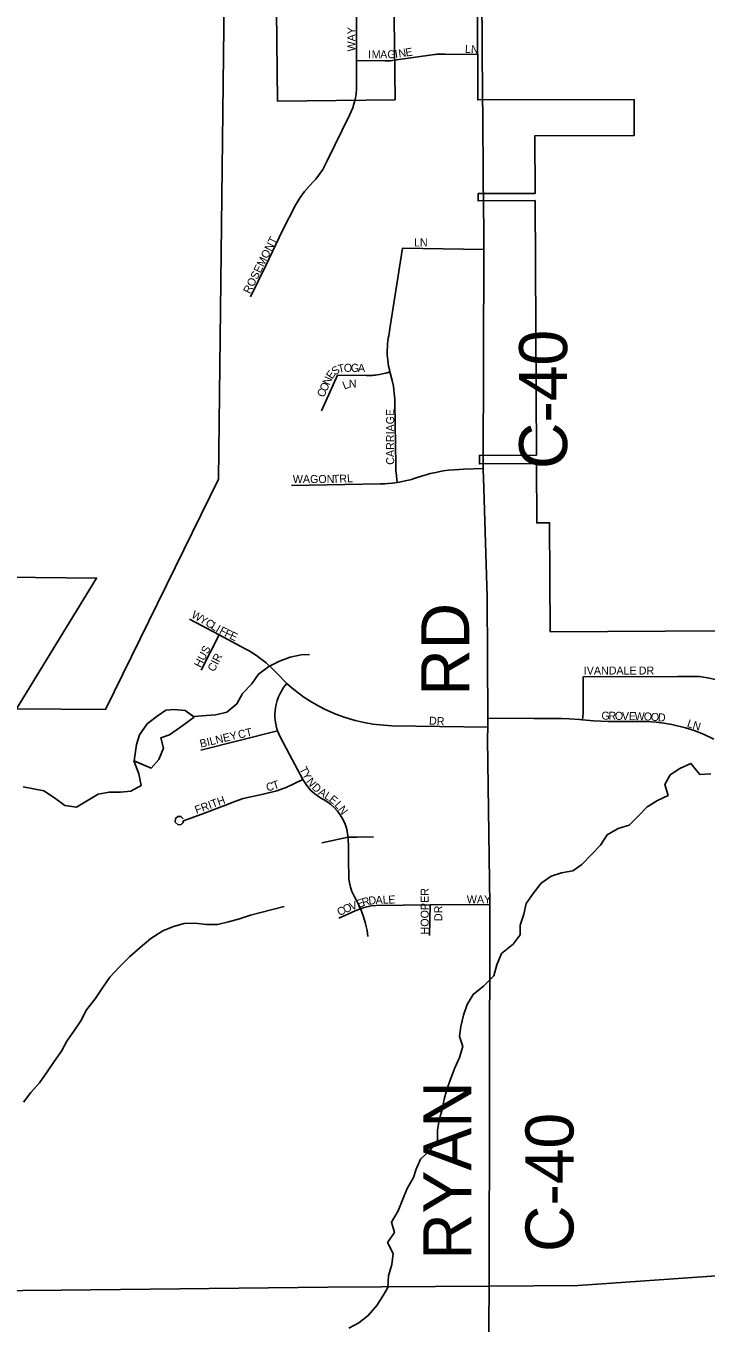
# Model space of a CAD drawing. Extents: x 1985906 to 2277390, y 930619 to 1324581.
# Drawn here: x 2135458 to 2139705, y 1129372 to 1137477 of the extents above; entities that cross this region are included whole.
import ezdxf

# ---------------------------------------------------------------- set-up
doc = ezdxf.new("R2010")
doc.units = 0
for name, color, linetype in [('GM_X_City_Street', 7, 'Continuous'), ('GM_X_Corporation', 7, 'Continuous'), ('GM_X_County_Road', 7, 'Continuous'), ('GM_X_County_Road_Text', 7, 'Continuous'), ('GM_X_Minor_Lake', 7, 'Continuous'), ('GM_X_Minor_River', 7, 'Continuous'), ('GM_X_State_Route', 7, 'Continuous'), ('GM_X_Township_Road', 7, 'Continuous'), ('GM_X_Township_Subdivision', 7, 'Continuous'), ('GM_X_Township_Subdivision_Text', 7, 'Continuous')]:
    doc.layers.add(name, color=color, linetype=linetype)

msp = doc.modelspace()

# ---------------------------------------------------------------- linework, layer by layer
at = {"layer": 'GM_X_City_Street'}
msp.add_lwpolyline([(2138315.1, 1134652.6), (2138313.4, 1134704.1)], dxfattribs=at)
at = {"layer": 'GM_X_Corporation'}
for points in [[(2136709.2, 1138705.4), (2136660.1, 1134644.9), (2135955.2, 1133206.6), (2135398.4, 1133209.2), (2135899.2, 1134027.1), (2135327.8, 1134032.4), (2135329.8, 1133491.3), (2133808.1, 1133465.9), (2133806.7, 1133847.6), (2132416.1, 1133842.6), (2132394.6, 1139746.5)], [(2137743.9, 1138716.9), (2137763, 1137016.1), (2137028.7, 1137007.9), (2137009.7, 1138708.7)], [(2139807.8, 1133697.6), (2138732, 1133691.9), (2138728.5, 1134372.3), (2138648.4, 1134371.9), (2138646.5, 1134742.1), (2138290.3, 1134740.2), (2138290.1, 1134793.3), (2138646.2, 1134795.2), (2138637.9, 1136386), (2138281.9, 1136384.2), (2138281.7, 1136429.2), (2138637.9, 1136430.7), (2138636.4, 1136790.9), (2139256.6, 1136793.4), (2139255.7, 1137018.5), (2138279.5, 1137014.5), (2138277.3, 1137590.2)]]:
    msp.add_lwpolyline(points, dxfattribs=at)
at = {"layer": 'GM_X_County_Road'}
for points in [[(2138306.9, 1137435.1), (2138305.7, 1137589.7)], [(2138311.6, 1136868.3), (2138308, 1137299.1), (2138306.9, 1137435.1)], [(2138316.5, 1136301.5), (2138311.6, 1136868.3)], [(2138313.4, 1134704.1), (2138313.1, 1134711.8), (2138318.4, 1136080.9), (2138316.9, 1136250)], [(2138316.9, 1136250), (2138316.5, 1136301.5)], [(2138351.4, 1129603.3), (2138354.8, 1131986.4), (2138341.2, 1133022.6), (2138341.8, 1133095.5), (2138341.6, 1133150.7), (2138339.2, 1133910.2), (2138315.1, 1134652.6)]]:
    msp.add_lwpolyline(points, dxfattribs=at)
at = {"layer": 'GM_X_Minor_Lake'}
for points in [[(2136131.4, 1132885.3), (2136240.6, 1132839.3), (2136288.7, 1132893.6), (2136316.5, 1132963.8), (2136300.2, 1133028), (2136354.4, 1133048.2), (2136416.5, 1133090.5), (2136508.4, 1133157.6)], [(2136510.7, 1133156.9), (2136452.3, 1133198.9), (2136381.9, 1133206.7), (2136331.7, 1133200.6), (2136277.6, 1133164.3), (2136215.5, 1133116), (2136167.5, 1133047.7), (2136147.7, 1132987.4), (2136133.5, 1132884.2)], [(2136509, 1133158.1), (2136452.3, 1133198.9), (2136381.9, 1133206.7), (2136331.7, 1133200.6), (2136277.6, 1133164.3), (2136215.5, 1133116), (2136167.5, 1133047.7), (2136147.7, 1132987.4), (2136133.6, 1132884.4)], [(2136133.6, 1132884.4), (2136240.6, 1132839.3), (2136288.7, 1132893.6), (2136316.5, 1132963.8), (2136300.2, 1133028), (2136354.4, 1133048.2), (2136416.5, 1133090.5), (2136509, 1133158.1)]]:
    msp.add_lwpolyline(points, dxfattribs=at)
at = {"layer": 'GM_X_Minor_River'}
for points in [[(2136509.5, 1133162), (2136584.3, 1133168.5), (2136644.7, 1133173.4), (2136713.3, 1133188.3), (2136774.5, 1133241.3), (2136809.7, 1133304.9), (2136869, 1133366), (2136910.3, 1133427.5), (2136975.4, 1133474.4), (2137042.2, 1133507.3), (2137109, 1133532.2), (2137177.5, 1133547), (2137227.8, 1133550.1)], [(2135441.5, 1132721.7), (2135505.6, 1132710.5), (2135569.7, 1132697.3), (2135637.2, 1132654), (2135700.7, 1132606.7), (2135772.8, 1132595.3), (2135845.9, 1132640.2), (2135908.9, 1132677.1), (2135977.4, 1132689.9), (2136047.7, 1132688.7), (2136112.1, 1132695.5), (2136177, 1132730.5), (2136162.1, 1132803), (2136132.4, 1132884.2)], [(2137474.1, 1129340.5), (2137536.9, 1129373.4), (2137596, 1129418.5), (2137649.3, 1129481.8), (2137688.6, 1129543.3), (2137717.6, 1129594.9), (2137722.9, 1129667), (2137742.1, 1129736.9), (2137751.4, 1129806.9), (2137716.4, 1129875.8), (2137759.7, 1129937.2), (2137740.7, 1130001.8), (2137782.1, 1130073.2), (2137811.5, 1130144.9), (2137838.8, 1130212.6), (2137878.2, 1130282.2), (2137895.2, 1130334), (2137922.3, 1130395.7), (2137979.5, 1130450.9), (2138028.8, 1130512.2), (2138027.9, 1130576.4), (2138039.1, 1130640.4), (2138058.3, 1130706.2), (2138069.5, 1130770.2), (2138088.7, 1130838.1), (2138114, 1130905.9), (2138137.2, 1130967.6), (2138166.4, 1131031.3), (2138185.7, 1131099.2), (2138164.7, 1131161.8), (2138173.8, 1131225.8), (2138191.1, 1131295.7), (2138214.3, 1131361.5), (2138251.6, 1131425), (2138314.8, 1131476.1), (2138380.2, 1131541.1), (2138399.5, 1131611), (2138428.8, 1131680.6), (2138500.2, 1131739.5), (2138545.3, 1131796.9), (2138544.4, 1131857.1), (2138567.7, 1131926.9), (2138582.9, 1131992.8), (2138626.2, 1132056.3), (2138675.5, 1132119.6), (2138738.6, 1132164.6), (2138803.2, 1132185.5), (2138873.8, 1132198.3), (2138930.7, 1132237.4), (2138990, 1132300.5), (2139045.3, 1132357.7), (2139088.6, 1132423.1), (2139157.6, 1132462), (2139226.2, 1132482.8), (2139283.5, 1132542), (2139338.7, 1132597.1), (2139401.7, 1132638.1), (2139468.5, 1132669), (2139447.6, 1132737.6), (2139480.8, 1132797.2), (2139541.8, 1132836.2), (2139610.6, 1132869.1), (2139667.7, 1132799.9), (2139736.1, 1132804.6)], [(2135443.5, 1130751.5), (2135488.7, 1130812.8), (2135542, 1130872.1), (2135591.4, 1130941.4), (2135634.7, 1131006.8), (2135680, 1131070.2), (2135713.3, 1131133.8), (2135760.7, 1131201.2), (2135799.9, 1131260.6), (2135835.2, 1131328.2), (2135890.6, 1131397.4), (2135936, 1131466.8), (2135981.4, 1131532.2), (2136042.8, 1131597.3), (2136104.1, 1131660.4), (2136171.5, 1131719.4), (2136238.7, 1131774.4), (2136311.9, 1131823.2), (2136378.6, 1131850.1), (2136445.3, 1131868.9), (2136513.6, 1131869.7), (2136585.8, 1131862.4), (2136654.1, 1131863.2), (2136722.6, 1131878), (2136791.3, 1131896.8), (2136860, 1131921.6), (2136924.6, 1131936.5), (2137069.9, 1131974)]]:
    msp.add_lwpolyline(points, dxfattribs=at)
at = {"layer": 'GM_X_State_Route'}
msp.add_lwpolyline([(2134482.4, 1129566.6), (2135677.7, 1129577.9), (2137342.7, 1129596.4), (2138351.4, 1129603.3), (2138906.3, 1129605.5), (2139800.4, 1129668.5), (2140031.3, 1129681.6), (2140403.4, 1129701.2), (2140677.6, 1129703.4), (2141339.2, 1129703.4), (2143801.5, 1129721.9)], dxfattribs=at)
at = {"layer": 'GM_X_Township_Road'}
msp.add_lwpolyline([(2138096.7, 1121368.5), (2138105.1, 1123243.7), (2138118.9, 1123374), (2138152.8, 1123504.5), (2138280.8, 1123765.4), (2138294.7, 1123827.6), (2138302.4, 1123968), (2138351.4, 1129603.3)], dxfattribs=at)
at = {"layer": 'GM_X_Township_Subdivision'}
for points in [[(2136859.4, 1135784.4), (2136955.1, 1135980.6), (2137061.2, 1136198.1), (2137141, 1136357), (2137171.3, 1136404.9), (2137198.4, 1136442), (2137228, 1136477.8), (2137253.4, 1136505.3), (2137267.5, 1136520.4), (2137311.2, 1136579.8), (2137329, 1136612.7), (2137339.5, 1136634.1), (2137481.1, 1136924.6), (2137489.9, 1136943.4), (2137498.8, 1136965.5), (2137506.5, 1136988.8), (2137514, 1137017.8), (2137519.7, 1137050), (2137522.7, 1137083.6), (2137523.2, 1137106.8), (2137523.2, 1137261.8), (2137523.2, 1137640.8)], [(2137523.2, 1137261.8), (2137699.2, 1137258.7), (2137706, 1137258.8), (2137714.2, 1137259), (2137723.6, 1137259.4), (2137734.2, 1137260.2), (2137747.3, 1137261.5), (2137757, 1137262.8), (2138008.6, 1137298.2), (2138014.9, 1137298.9), (2138024.1, 1137299.9), (2138034.5, 1137300.7), (2138046.7, 1137301.4), (2138058.4, 1137301.6), (2138078.4, 1137301.3), (2138278.4, 1137297.8)], [(2137777.1, 1134624.6), (2137772.4, 1134664.1), (2137771.4, 1134671.7), (2137770.1, 1134683.6), (2137768.9, 1134698.1), (2137768.4, 1134705.9), (2137767.7, 1134724.1), (2137767.6, 1134732.9), (2137761, 1135119.1), (2137761, 1135131.1), (2137760.8, 1135145.3), (2137759.9, 1135163.9), (2137758.6, 1135181.5), (2137756.2, 1135203.6), (2137752.8, 1135226.3), (2137745.6, 1135262.6), (2137735.6, 1135300.4), (2137730.8, 1135314.9), (2137727.7, 1135329.4), (2137723.1, 1135351.1), (2137720, 1135369), (2137717.4, 1135387.9), (2137715.8, 1135404.4), (2137714.6, 1135422.9), (2137714.1, 1135447.5), (2137715, 1135475.4), (2137716.2, 1135490), (2137718, 1135507), (2137720.8, 1135526.2), (2137723.3, 1135540.8), (2137732.8, 1135600.1), (2137810.4, 1136089.2), (2138318.4, 1136080.9)], [(2137304.5, 1135071.3), (2137404.2, 1135295.2), (2137585.3, 1135292), (2137591, 1135292), (2137597, 1135292.1), (2137602.8, 1135292.3), (2137608.9, 1135292.5), (2137613, 1135292.7), (2137617.8, 1135293), (2137623.3, 1135293.4), (2137630.2, 1135294), (2137641.8, 1135295.3), (2137650.7, 1135296.4), (2137665, 1135298.7), (2137684.7, 1135302.6), (2137704.4, 1135307.4), (2137714.1, 1135310.1), (2137730.8, 1135314.9)], [(2137117.3, 1134605.8), (2137671.5, 1134615.3), (2137686.8, 1134615.8), (2137698.9, 1134616.3), (2137717.6, 1134617.5), (2137746.3, 1134620.3), (2137777.1, 1134624.6), (2137791.2, 1134626.9), (2137808, 1134630), (2137826.7, 1134634), (2137846.8, 1134638.8), (2137865.8, 1134643.9), (2137888.4, 1134651), (2137908.2, 1134657.2), (2137929.3, 1134664.3), (2137956.9, 1134672.6), (2137982.3, 1134679.5), (2138006.7, 1134685.3), (2138035.7, 1134691.3), (2138064.6, 1134696.3), (2138095.6, 1134700.6), (2138131.6, 1134704.2), (2138161.7, 1134706.1), (2138190.9, 1134707), (2138313.1, 1134711.8)], [(2136478.9, 1133770.8), (2136664.4, 1133672.2), (2136832.1, 1133583), (2136852.8, 1133571.6), (2136875.9, 1133557.6), (2136898, 1133543.1), (2136925.7, 1133523.2), (2136957.4, 1133497.7), (2136993.5, 1133464.6), (2137022.8, 1133434.1), (2137087.9, 1133369), (2137121.3, 1133339.5), (2137159, 1133309.2), (2137194.4, 1133283.4), (2137232.4, 1133258.3), (2137272.4, 1133234.3), (2137322.1, 1133208), (2137394.1, 1133175.9), (2137451.2, 1133155), (2137513.9, 1133136.4), (2137569.3, 1133123.7), (2137624.8, 1133114.2), (2137692.7, 1133106.9), (2137742.4, 1133104.5), (2138341.8, 1133095.5)], [(2136552.2, 1133452.2), (2136664.4, 1133672.2)], [(2138934, 1133141.1), (2138937.8, 1133182.3), (2138938.9, 1133410.2)], [(2138938.9, 1133410.2), (2139529.6, 1133412.6), (2139635.1, 1133412.9), (2139664.6, 1133411.5), (2139726.6, 1133400.8), (2139762.5, 1133393)], [(2137594, 1131787.2), (2137588.5, 1131825.2), (2137577.3, 1131875.7), (2137566.9, 1131910.4), (2137553.8, 1131945.8), (2137547.5, 1131960.7), (2137532.3, 1131992.9), (2137507.3, 1132038.5), (2137493.5, 1132069.3), (2137484.9, 1132095.4), (2137478.9, 1132121.7), (2137475.1, 1132149.3), (2137473.9, 1132172), (2137472.9, 1132248.2), (2137471.6, 1132352.7), (2137470.8, 1132396.1), (2137470, 1132407.5), (2137467.2, 1132429.2), (2137461.1, 1132457.7), (2137450.7, 1132489.7), (2137439, 1132515.9), (2137420.9, 1132547), (2137403.2, 1132570.9), (2137383, 1132593.2), (2137362.8, 1132611.6), (2137344.1, 1132625.9), (2137320.8, 1132640.8), (2137299.7, 1132652.5), (2137284.2, 1132662.2), (2137262.3, 1132678.3), (2137240, 1132698.2), (2137224.2, 1132715.1), (2137207, 1132737), (2137187.3, 1132768.7), (2137103.4, 1132923.9), (2137041.2, 1133042.4), (2137036.4, 1133054), (2137030, 1133071.6), (2137023.5, 1133092.7), (2137018, 1133117.2), (2137014.8, 1133139.2), (2137013.3, 1133160.3), (2137013.2, 1133176.5), (2137014.5, 1133199.2), (2137018.8, 1133229), (2137027.2, 1133261.5), (2137035.3, 1133284), (2137043.6, 1133302.6), (2137067.1, 1133342.5), (2137087.9, 1133369)], [(2138341.6, 1133150.7), (2138629.8, 1133148.6), (2138754.7, 1133148.7), (2138804.1, 1133148.7), (2138850.1, 1133147.7), (2138915, 1133142.8), (2138934, 1133141.1), (2139003, 1133134.8), (2139097, 1133130.6), (2139233.9, 1133131), (2139334.2, 1133130.5), (2139393.3, 1133126.5), (2139442, 1133120.6), (2139492.7, 1133111.8), (2139577.6, 1133091), (2139631.5, 1133073.6), (2139689.1, 1133051), (2139754.2, 1133020.5)], [(2136549.8, 1132951.8), (2137030, 1133071.6)], [(2136440.2, 1132522.9), (2136426.2, 1132537.6), (2136406.3, 1132537.6), (2136392.3, 1132523.7), (2136390.8, 1132502.3), (2136408.5, 1132486.1), (2136427.6, 1132487.6), (2136438.7, 1132497.1), (2136442.4, 1132510.4), (2136573.7, 1132558.7), (2136703.4, 1132608.4), (2136762.3, 1132631), (2136814.4, 1132648.9), (2136939.2, 1132676.5), (2137025, 1132698.4), (2137086.7, 1132720.2), (2137187.3, 1132768.7)], [(2137305.6, 1132373.6), (2137470, 1132407.5)], [(2137470, 1132407.5), (2137501.9, 1132408.9), (2137525.2, 1132408.9), (2137554.6, 1132409.2), (2137629.1, 1132408.3)], [(2137411.7, 1131902.5), (2137463.3, 1131925.2), (2137495.2, 1131939.3), (2137524.1, 1131951.9), (2137547.5, 1131960.7), (2137571, 1131968.5), (2137613.4, 1131978.5), (2137645.8, 1131980.8), (2137982.1, 1131985), (2138354.8, 1131986.4)], [(2137979, 1131793.8), (2137982.1, 1131985)]]:
    msp.add_lwpolyline(points, dxfattribs=at)

# ---------------------------------------------------------------- texts
at = {"layer": 'GM_X_County_Road_Text'}
for s, p in [('C-40', (2138838.1, 1134708.5)), ('RD', (2138226.4, 1133291.7)), ('RYAN', (2138239.5, 1129767.3)), ('C-40', (2138877.7, 1129815.7))]:
    msp.add_text(s, height=300, rotation=90, dxfattribs=at).set_placement(p)
at = {"layer": 'GM_X_Township_Subdivision_Text'}
for s, rotation, p in [('WAY', 90, (2137515.5, 1137317.7)), ('LN', 356.82219, (2138198.6, 1137309.5)), ('I', 0.08741, (2137595.3, 1137274.3)), ('M', 0.07285, (2137617.3, 1137274.3)), ('A', 0.06558, (2137670.1, 1137274.4)), ('G', 1.66033, (2137715.6, 1137274.5)), ('I', 7.22228, (2137764.9, 1137276.2)), ('N', 8.61689, (2137788, 1137279.1)), ('E', 8.75272, (2137831.7, 1137285.7)), ('ROSEMONT', 63.43494, (2136856.5, 1135799.5)), ('LN', 0.00001, (2137881.3, 1136099.5)), ('S', 32.88669, (2137386.2, 1135292)), ('T', 10.96223, (2137411.1, 1135309.3)), ('O', 0.00001, (2137443.1, 1135315.7)), ('G', 0.00001, (2137487.1, 1135315.7)), ('A', 0.00001, (2137531.1, 1135315.7)), ('N', 65.77338, (2137352.7, 1135228.8)), ('E', 54.81115, (2137369.5, 1135266.7)), ('L', 21.57308, (2137446.6, 1135204.6)), ('N', 1.79264, (2137474.9, 1135216.6)), ('C', 65.77338, (2137318.4, 1135152.6)), ('O', 65.77338, (2137334.7, 1135188.7)), ('CARRIAGE', 90, (2137757.5, 1134734.9)), ('WAGON', 0.00001, (2137124.5, 1134621.1)), ('TRL', 2.20131, (2137374.9, 1134621.1)), ('W', 329.6879, (2136486.8, 1133783.8)), ('Y', 329.66963, (2136536.2, 1133755)), ('C', 329.70206, (2136574.2, 1133732.7)), ('L', 329.66883, (2136608.4, 1133712.7)), ('I', 330.32379, (2136639.3, 1133694.7)), ('F', 332.92535, (2136660.6, 1133682.6)), ('F', 334.4409, (2136693.3, 1133665.9)), ('E', 334.54809, (2136725.1, 1133650.7)), ('HUS', 62.52611, (2136548.5, 1133463.2)), ('CIR', 63.43931, (2136634.2, 1133437.9)), ('IVANDALE', 0.00001, (2138941.7, 1133424.3)), ('DR', 0.00001, (2139284.9, 1133424.3)), ('DR', 356.98902, (2137974.2, 1133111.9)), ('G', 359.08195, (2139051.8, 1133142.7)), ('R', 359.07713, (2139095.8, 1133142)), ('O', 359.11446, (2139135.5, 1133141.4)), ('V', 359.08195, (2139179.4, 1133140.7)), ('E', 359.07111, (2139223.4, 1133140)), ('W', 359.10252, (2139258.6, 1133139.4)), ('O', 356.98262, (2139315.4, 1133138.5)), ('O', 355.60297, (2139359, 1133136.2)), ('D', 356.08567, (2139403.3, 1133132.8)), ('BILNEY', 13.76199, (2136550.3, 1132966.4)), ('CT', 12.52109, (2136788.1, 1133023.7)), ('L', 342.08355, (2139582.8, 1133098.2)), ('N', 343.87728, (2139617.9, 1133086.9)), ('T', 296.99263, (2137163.6, 1132833.8)), ('Y', 299.2577, (2137180.6, 1132800.5)), ('C', 13.95379, (2136964.2, 1132693.7)), ('T', 18.47303, (2137006.8, 1132704.5)), ('N', 307.31525, (2137206.3, 1132755.7)), ('D', 317.02355, (2137239.2, 1132713.8)), ('FRITH', 20.22379, (2136522.8, 1132552.5)), ('A', 327.50008, (2137279.2, 1132677.7)), ('L', 328.70294, (2137317.3, 1132653.5)), ('E', 320.78556, (2137345.9, 1132636.3)), ('L', 312.46849, (2137381.4, 1132606.3)), ('N', 306.82618, (2137404.3, 1132581.3)), ('V', 20.35653, (2137490.2, 1131948.8)), ('E', 19.09151, (2137531.2, 1131964)), ('R', 15.8153, (2137563.7, 1131975.2)), ('D', 6.30641, (2137599.7, 1131985.6)), ('A', 1.92372, (2137642.4, 1131990.4)), ('L', 1.50312, (2137686.3, 1131991.9)), ('E', 1.52591, (2137721.5, 1131992.8)), ('HOOPER', 90, (2137973.1, 1131800.1)), ('WAY', 0.00001, (2138211.3, 1131994.3)), ('C', 25.10934, (2137415.3, 1131914.2)), ('O', 24.35531, (2137451, 1131931)), ('DR', 90, (2138058.2, 1131883.7))]:
    msp.add_text(s, height=50, rotation=rotation, dxfattribs=at).set_placement(p)

doc.saveas('drawing.dxf')
